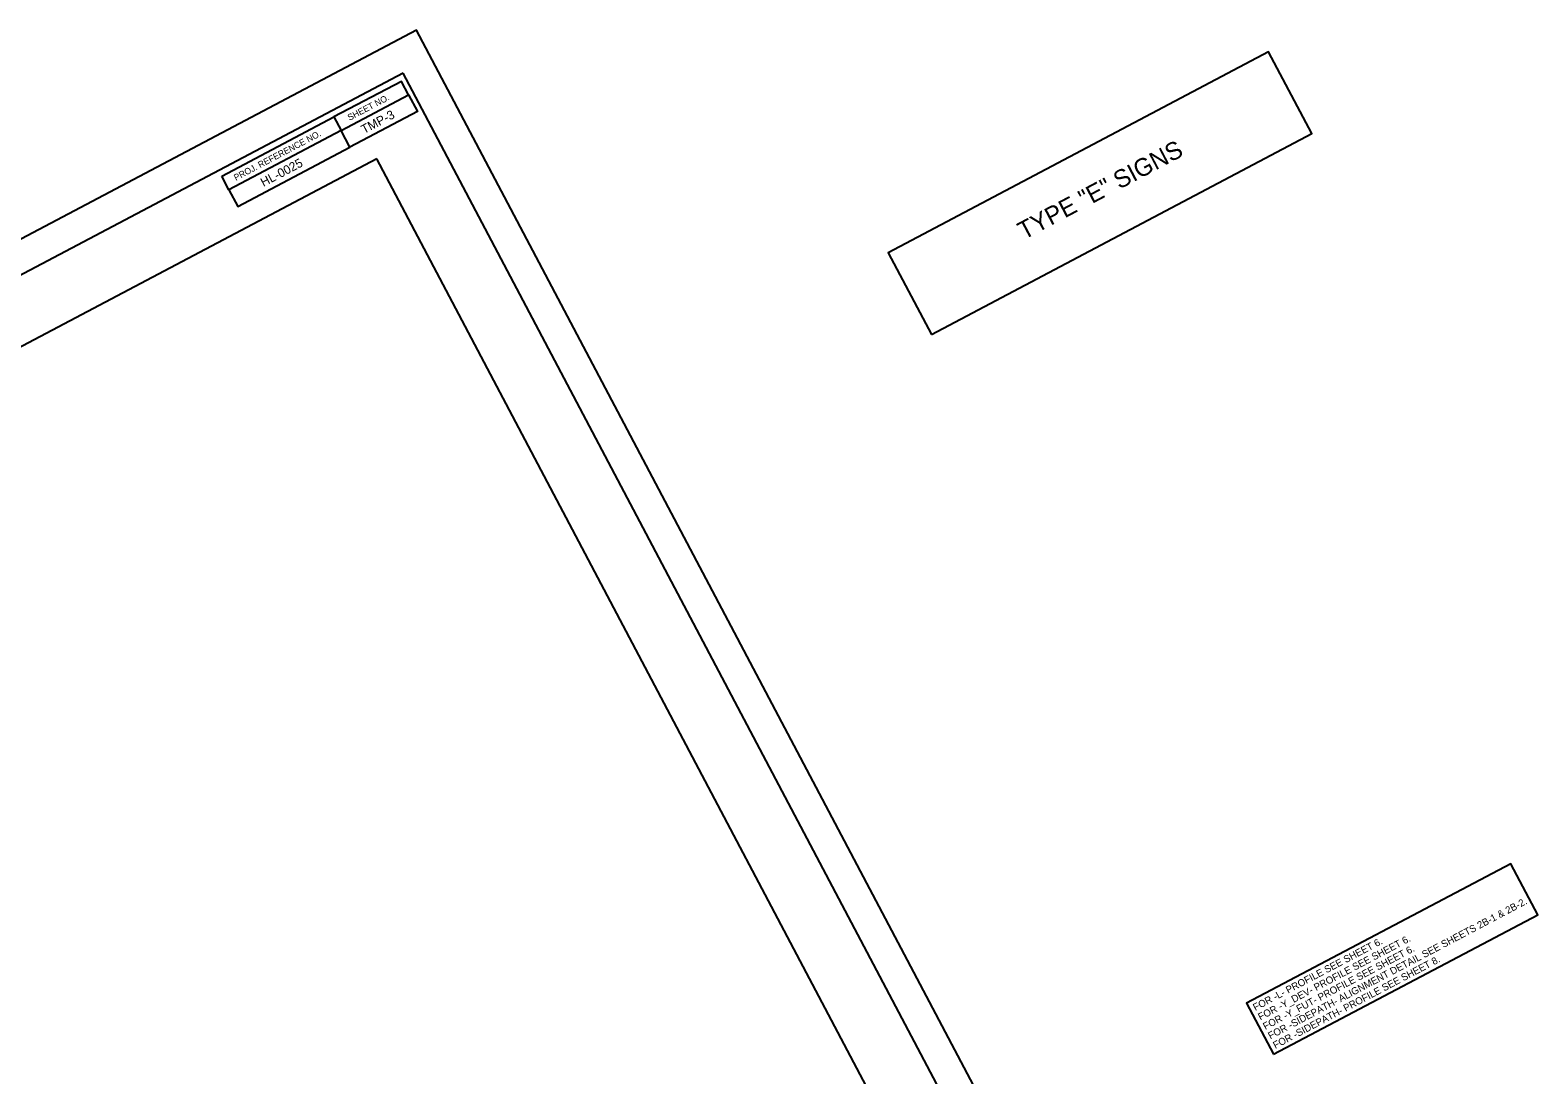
# Model space of a CAD drawing. Extents: x 1789 to 1487599, y -706 to 498569.
# Drawn here: x 2978 to 4166, y 232 to 1055 of the extents above; entities that cross this region are included whole.
import ezdxf

# ---------------------------------------------------------------- set-up
doc = ezdxf.new("R2010")
doc.units = 0
for name, color, linetype in [('DEV BORDER CELL', 7, 'Continuous'), ('Prop Grid Mask', 7, 'Continuous'), ('Prop Horizontal Alignment Curve and Spiral Data', 7, 'Continuous'), ('Scratch_Level_0', 7, 'Continuous'), ('Sheet Block Title CELL', 7, 'Continuous'), ('Sheet Plot Border Outside CELL', 7, 'Continuous'), ('Sheet Title CELL', 7, 'Continuous')]:
    doc.layers.add(name, color=color, linetype=linetype)

msp = doc.modelspace()

# ---------------------------------------------------------------- linework, layer by layer
at = {"layer": 'DEV BORDER CELL'}
msp.add_line((3222.6, 976.4), (3275.7, 1004.4), dxfattribs=at)
for points in [[(3271.5, 1021.6), (1945.1, 321.2), (2435.4, -607.3), (3761.8, 93.1)], [(3222.6, 976.4), (3275.7, 1004.4), (3270.1, 1015), (3217, 987)], [(3222.6, 976.4), (3275.7, 1004.4), (3282.7, 991.2), (3229.6, 963.1)], [(3128.6, 940.3), (3217, 987), (3222.6, 976.4), (3134.2, 929.7)], [(3222.6, 976.4), (3134.2, 929.7), (3141.2, 916.4), (3229.6, 963.1)]]:
    msp.add_lwpolyline(points, close=True, dxfattribs=at)
at = {"layer": 'Prop Grid Mask'}
msp.add_lwpolyline([(3957.5, 248.4), (4165.8, 358.4), (4144.5, 398.6), (3936.2, 288.6)], close=True, dxfattribs=at)
at = {"layer": 'Scratch_Level_0'}
msp.add_lwpolyline([(3250.7, 954), (2012.7, 300.3), (2456.2, -539.7), (3233.4, -129.4), (3178.2, -24.8), (3639, 218.5)], close=True, dxfattribs=at)
at = {"layer": 'Sheet Block Title CELL'}
msp.add_lwpolyline([(3687.8, 815.6), (3987.7, 973.9), (3953.6, 1038.4), (3653.7, 880)], close=True, dxfattribs=at)
at = {"layer": 'Sheet Plot Border Outside CELL'}
msp.add_lwpolyline([(2302.9, -705.5), (3795.6, 82.7), (3282, 1055.4), (1789.3, 267.2)], close=True, dxfattribs=at)

# ---------------------------------------------------------------- texts
at = {"layer": 'DEV BORDER CELL'}
for s, height, rotation, p in [('SHEET NO.', 5, 27.8356, (3229.3, 983.9)), ('TMP-3', 7, 27.8351, (3240.7, 973.5)), ('PROJ. REFERENCE NO.', 4.999, 27.8356, (3139.7, 936.6)), ('HL-0025', 7, 27.8351, (3161.4, 931.8))]:
    msp.add_text(s, height=height, rotation=rotation, dxfattribs=at).set_placement(p)
at = {"layer": 'Prop Horizontal Alignment Curve and Spiral Data'}
for s, p in [('FOR -SIDEPATH- ALIGNMENT DETAIL SEE SHEETS 2B-1 & 2B-2.', (3955, 260.1)), ('FOR -L- PROFILE SEE SHEET 6.', (3943.1, 282.5)), ('FOR -Y_DEV- PROFILE SEE SHEET 6.', (3947.1, 275)), ('FOR -Y_FUT- PROFILE SEE SHEET 6.', (3951, 267.5)), ('FOR -SIDEPATH- PROFILE SEE SHEET 8.', (3958.9, 252.6))]:
    msp.add_text(s, height=5.625, rotation=27.8351, dxfattribs=at).set_placement(p)
at = {"layer": 'Sheet Title CELL'}
msp.add_text('TYPE "E" SIGNS', height=14, rotation=27.8343, dxfattribs=at).set_placement((3760.7, 890))

doc.saveas('drawing.dxf')
